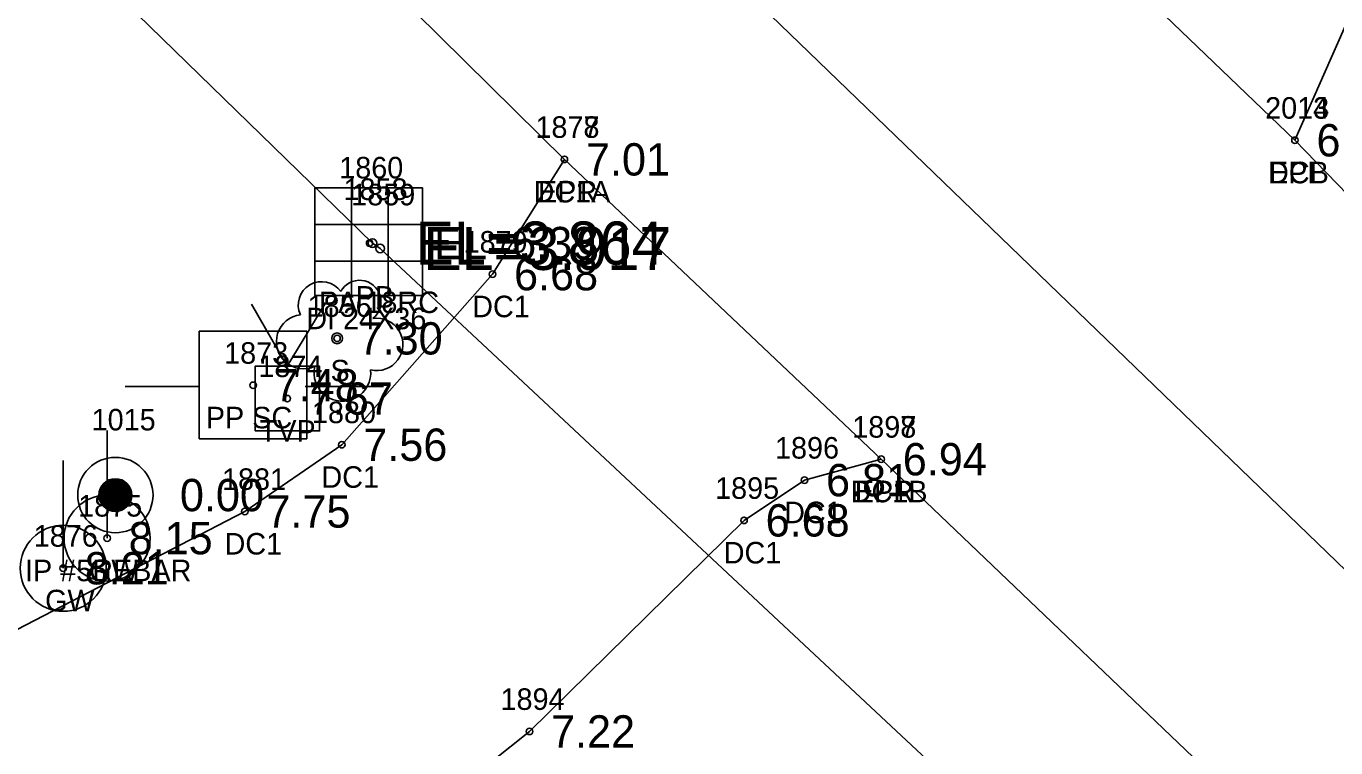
# Model space of a CAD drawing. Extents: x 2608598 to 2610682, y 641451 to 643526.
# Drawn here: x 2609158.2 to 2609219, y 642975 to 643008.5 of the extents above; entities that cross this region are included whole.
import ezdxf

# ---------------------------------------------------------------- set-up
doc = ezdxf.new("R2010")
doc.units = 0
for name, color, linetype in [('RD_EX_Conc', 7, 'Continuous'), ('RD_EX_Conc_txCode', 7, 'Continuous'), ('RD_EX_DR_Inlet', 7, 'Continuous'), ('RD_EX_DR_Inlet_txCode', 7, 'Continuous'), ('RD_EX_DR_Pipe', 7, 'Continuous'), ('RD_EX_DR_Pipe_txCode', 7, 'Continuous'), ('RD_EX_DV_Prop_txCode', 7, 'Continuous'), ('RD_EX_DV_PropPin', 7, 'Continuous'), ('RD_EX_Road', 7, 'Continuous'), ('RD_EX_Road_txCode', 7, 'Continuous'), ('RD_EX_TX_Conc_ELEV', 7, 'Continuous'), ('RD_EX_TX_DR_Inlet_ELEV', 7, 'Continuous'), ('RD_EX_TX_DV_Prop_ELEV', 7, 'Continuous'), ('RD_EX_TX_Road_ELEV', 7, 'Continuous'), ('RD_EX_TX_UT_ELEV', 7, 'Continuous'), ('RD_EX_TX_VEG_ELEV', 7, 'Continuous'), ('RD_EX_UT', 7, 'Continuous'), ('RD_EX_UT_txCode', 7, 'Continuous'), ('RD_EX_VEG', 7, 'Continuous'), ('RD_EX_VEG_txCode', 7, 'Continuous'), ('RD_HC_Cl', 7, 'Continuous'), ('RD_HC_Survey_ELEV', 7, 'Continuous'), ('RD_SMD_Locator', 7, 'Continuous'), ('RD_TX_Pipe_ElevEX', 7, 'Continuous')]:
    doc.layers.add(name, color=color, linetype=linetype)

msp = doc.modelspace()

# ---------------------------------------------------------------- linework, layer by layer
at = {"layer": 'RD_EX_Conc'}
for points in [[(2609269.998, 643061.086), (2609272.605, 643058.59), (2609260.564, 643044.702), (2609257.72, 643041.969), (2609255.041, 643040.51), (2609251.591, 643039.846), (2609247.634, 643039.744), (2609244.983, 643039.005), (2609242.031, 643037.037), (2609225.849, 643019.544), (2609223.428, 643016.615), (2609221.422, 643012.887), (2609217.132, 643003.172)], [(2609183.195, 643002.284), (2609179.855, 642996.956), (2609172.851, 642989.038), (2609168.35, 642985.939), (2609153.064, 642978.036), (2609140.288, 642969.219), (2609118.234, 642952.787)], [(2609162.68, 642959.754), (2609163.773, 642962.47), (2609165.522, 642965.128), (2609168.171, 642967.213), (2609174.254, 642970.662), (2609178.069, 642972.943), (2609181.572, 642975.727), (2609191.54, 642985.525), (2609194.348, 642987.393), (2609197.913, 642988.365)]]:
    msp.add_lwpolyline(points, dxfattribs=at)
at = {"layer": 'RD_EX_DR_Inlet'}
for p, q in [((2609173.304, 643000.957), (2609173.304, 642995.957)), ((2609175.004, 643000.957), (2609175.004, 642995.957)), ((2609171.604, 642999.257), (2609176.604, 642999.257)), ((2609171.604, 642997.557), (2609176.604, 642997.557))]:
    msp.add_line(p, q, dxfattribs=at)
msp.add_lwpolyline([(2609171.604, 642995.957), (2609171.604, 643000.957), (2609176.604, 643000.957), (2609176.604, 642995.957)], close=True, dxfattribs=at)
at = {"layer": 'RD_EX_DR_Pipe'}
msp.add_lwpolyline([(2609067.894, 643101.844), (2609174.278, 642998.399), (2609174.637, 642998.15), (2609264.347, 642914.358)], dxfattribs=at)
at = {"layer": 'RD_EX_DV_PropPin'}
for p, q in [((2609161.667, 642986.33), (2609161.667, 642987.069)), ((2609161.702, 642986.273), (2609161.702, 642987.126)), ((2609161.737, 642986.226), (2609161.737, 642987.174)), ((2609161.772, 642986.185), (2609161.772, 642987.215)), ((2609161.807, 642986.149), (2609161.807, 642987.25)), ((2609161.842, 642986.118), (2609161.842, 642987.282)), ((2609161.877, 642986.09), (2609161.877, 642987.31)), ((2609161.912, 642986.065), (2609161.912, 642987.334)), ((2609161.947, 642986.043), (2609161.947, 642987.356)), ((2609161.982, 642986.024), (2609161.982, 642987.375)), ((2609162.017, 642986.007), (2609162.017, 642987.392)), ((2609162.052, 642985.992), (2609162.052, 642987.407)), ((2609162.087, 642985.979), (2609162.087, 642987.42)), ((2609162.122, 642985.968), (2609162.122, 642987.431)), ((2609162.157, 642985.959), (2609162.157, 642987.44)), ((2609162.192, 642985.952), (2609162.192, 642987.448)), ((2609162.227, 642985.946), (2609162.227, 642987.453)), ((2609162.262, 642985.942), (2609162.262, 642987.457)), ((2609162.297, 642985.939), (2609162.297, 642987.46)), ((2609162.332, 642985.939), (2609162.332, 642987.461)), ((2609162.367, 642985.939), (2609162.367, 642987.46)), ((2609162.402, 642985.942), (2609162.402, 642987.457)), ((2609162.437, 642985.946), (2609162.437, 642987.453)), ((2609162.472, 642985.952), (2609162.472, 642987.448)), ((2609162.507, 642985.959), (2609162.507, 642987.44)), ((2609162.542, 642985.968), (2609162.542, 642987.431)), ((2609162.577, 642985.979), (2609162.577, 642987.42)), ((2609162.612, 642985.992), (2609162.612, 642987.407)), ((2609162.647, 642986.007), (2609162.647, 642987.392)), ((2609162.682, 642986.024), (2609162.682, 642987.375)), ((2609162.717, 642986.043), (2609162.717, 642987.356)), ((2609162.752, 642986.065), (2609162.752, 642987.334)), ((2609162.787, 642986.09), (2609162.787, 642987.31)), ((2609162.822, 642986.118), (2609162.822, 642987.282)), ((2609162.857, 642986.149), (2609162.857, 642987.25)), ((2609162.893, 642986.185), (2609162.893, 642987.215)), ((2609162.928, 642986.226), (2609162.928, 642987.174)), ((2609162.963, 642986.273), (2609162.963, 642987.126)), ((2609162.998, 642986.33), (2609162.998, 642987.069)), ((2609161.597, 642986.504), (2609161.597, 642986.896)), ((2609161.632, 642986.402), (2609161.632, 642986.998)), ((2609163.033, 642986.402), (2609163.033, 642986.998)), ((2609163.068, 642986.504), (2609163.068, 642986.896))]:
    msp.add_line(p, q, dxfattribs=at)
for radius in [1.75, 0.761]:
    msp.add_circle((2609162.332, 642986.7), radius, dxfattribs=at)
at = {"layer": 'RD_EX_Road'}
for points in [[(2608806.889, 643364.989), (2608810.184, 643361.1), (2608820.754, 643351.249), (2608881.81, 643292.235), (2608917.833, 643257.495), (2608933.208, 643242.709), (2608954.068, 643222.833), (2609026.064, 643154.189), (2609039.601, 643139.963), (2609073.879, 643106.954), (2609100.48, 643081.888), (2609124.194, 643058.866), (2609171.612, 643013.711), (2609183.195, 643002.284), (2609197.913, 642988.365), (2609247.586, 642940.954), (2609328.02, 642863.599), (2609402.609, 642790.299), (2609474.235, 642720.69), (2609483.838, 642711.579), (2609495.782, 642699.917), (2609509.808, 642686.45)], [(2609042.495, 643170.94), (2609058.512, 643155.458), (2609096.06, 643119.372), (2609116.51, 643099.11), (2609162.396, 643055.351), (2609177.209, 643041.342), (2609188.353, 643030.959), (2609199.912, 643019.764), (2609205.803, 643014.044), (2609217.132, 643003.172), (2609235.835, 642983.899), (2609237.032, 642983.51), (2609256.803, 642965.042), (2609258.491, 642962.514), (2609263.653, 642957.664), (2609344.713, 642879.888)]]:
    msp.add_lwpolyline(points, dxfattribs=at)
at = {"layer": 'RD_EX_UT'}
for p, q in [((2609170.321, 642992.678), (2609168.655, 642995.564)), ((2609170.321, 642992.678), (2609172.062, 642995.564)), ((2609171.223, 642994.306), (2609166.223, 642994.306)), ((2609166.223, 642994.306), (2609166.223, 642989.306)), ((2609171.223, 642989.306), (2609171.223, 642994.306)), ((2609162.791, 642991.744), (2609166.261, 642991.744)), ((2609171.151, 642991.744), (2609174.791, 642991.744)), ((2609161.949, 642984.701), (2609161.949, 642989.701)), ((2609166.223, 642989.306), (2609171.223, 642989.306)), ((2609159.91, 642983.303), (2609159.91, 642988.303))]:
    msp.add_line(p, q, dxfattribs=at)
msp.add_lwpolyline([(2609168.821, 642989.678), (2609168.821, 642992.678), (2609171.821, 642992.678), (2609171.821, 642989.678)], close=True, dxfattribs=at)
for centre in [(2609161.949, 642984.701), (2609159.91, 642983.303)]:
    msp.add_circle(centre, 1.999, dxfattribs=at)
at = {"layer": 'RD_EX_VEG'}
msp.add_circle((2609172.633, 642993.975), 0.25, dxfattribs=at)
for centre, radius, start, end in [((2609171.912, 642995.522), 1.084, 34.97629, 204.75602), ((2609173.678, 642995.677), 0.995, 308.76261, 152.04674), ((2609171.069, 642993.819), 1.257, 96.45179, 294.73401), ((2609174.472, 642993.696), 1.218, 256.56668, 98.10463), ((2609172.878, 642992.379), 1.318, 166.88266, 5.75893)]:
    msp.add_arc(centre, radius, start, end, dxfattribs=at)
at = {"layer": 'RD_HC_Cl'}
msp.add_line((2608814.812, 643373.733), (2610092.394, 642140.787), dxfattribs=at)
at = {"layer": 'RD_SMD_Locator'}
for centre, radius in [((2609217.132, 643003.172), 0.15), ((2609217.132, 643003.172), 0.15), ((2609183.195, 643002.284), 0.15), ((2609183.195, 643002.284), 0.15), ((2609174.142, 642998.399), 0.15), ((2609174.278, 642998.399), 0.2), ((2609174.637, 642998.15), 0.2), ((2609179.855, 642996.956), 0.15), ((2609172.633, 642993.975), 0.15), ((2609168.732, 642991.797), 0.15), ((2609170.321, 642991.178), 0.15), ((2609172.851, 642989.038), 0.15), ((2609197.913, 642988.365), 0.15), ((2609197.913, 642988.365), 0.15), ((2609194.348, 642987.393), 0.15), ((2609162.332, 642986.7), 0.15), ((2609168.35, 642985.939), 0.15), ((2609191.54, 642985.525), 0.15), ((2609161.949, 642984.701), 0.15), ((2609159.91, 642983.303), 0.15), ((2609181.572, 642975.727), 0.15)]:
    msp.add_circle(centre, radius, dxfattribs=at)

# ---------------------------------------------------------------- texts
at = {"layer": 'RD_EX_Conc_txCode'}
for s, p in [('2013', (2609215.747, 643004.172)), ('1878', (2609181.848, 643003.284)), ('DCB', (2609215.881, 643001.172)), ('DC1A', (2609181.762, 643000.284)), ('1879', (2609178.509, 642997.956)), ('DC1', (2609178.91, 642994.956)), ('1880', (2609171.465, 642990.038)), ('1897', (2609196.566, 642989.365)), ('1896', (2609192.978, 642988.393)), ('1881', (2609167.287, 642986.939)), ('DC1', (2609171.906, 642987.038)), ('1895', (2609190.194, 642986.525)), ('DC1B', (2609196.495, 642986.365)), ('DC1', (2609193.403, 642985.393)), ('DC1', (2609167.405, 642983.939)), ('DC1', (2609190.595, 642983.525)), ('1894', (2609180.226, 642976.727))]:
    msp.add_text(s, height=1, dxfattribs=at).set_placement(p)
at = {"layer": 'RD_EX_DR_Inlet_txCode'}
for s, p in [('1860', (2609172.733, 643001.399)), ('DI 24X36', (2609171.205, 642994.399))]:
    msp.add_text(s, height=1, dxfattribs=at).set_placement(p)
at = {"layer": 'RD_EX_DR_Pipe_txCode'}
for s, p in [('1858', (2609172.931, 643000.399)), ('1859', (2609173.29, 643000.15)), ('PB', (2609173.498, 642995.399)), ('PA 18RC', (2609171.794, 642995.15))]:
    msp.add_text(s, height=1, dxfattribs=at).set_placement(p)
at = {"layer": 'RD_EX_DV_Prop_txCode'}
for s, p in [('1015', (2609161.23, 642989.7)), ('IP #5REBAR', (2609158.135, 642982.7))]:
    msp.add_text(s, height=1, dxfattribs=at).set_placement(p)
at = {"layer": 'RD_EX_Road_txCode'}
for s, p in [('2014', (2609215.747, 643004.172)), ('1877', (2609181.848, 643003.284)), ('EPL', (2609215.928, 643001.172)), ('EPR', (2609181.966, 643000.284)), ('1898', (2609196.566, 642989.365)), ('EPR', (2609196.684, 642986.365))]:
    msp.add_text(s, height=1, dxfattribs=at).set_placement(p)
at = {"layer": 'RD_EX_TX_Conc_ELEV'}
for s, p in [('6.82', (2609218.132, 643002.422)), ('7.01', (2609184.195, 643001.534)), ('6.68', (2609180.855, 642996.206)), ('7.56', (2609173.851, 642988.288)), ('6.94', (2609198.913, 642987.615)), ('6.81', (2609195.348, 642986.643)), ('7.75', (2609169.35, 642985.189)), ('6.68', (2609192.54, 642984.775)), ('7.22', (2609182.572, 642974.977))]:
    msp.add_text(s, height=1.5, dxfattribs=at).set_placement(p)
at = {"layer": 'RD_EX_TX_DR_Inlet_ELEV'}
msp.add_text('EL=6.39', height=1.5, dxfattribs=at).set_placement((2609177.142, 642997.649))
at = {"layer": 'RD_EX_TX_DV_Prop_ELEV'}
msp.add_text('0.00', height=1.5, dxfattribs=at).set_placement((2609165.332, 642985.95))
at = {"layer": 'RD_EX_TX_Road_ELEV'}
for s, p in [('6.82', (2609218.132, 643002.422)), ('7.01', (2609184.195, 643001.534)), ('6.94', (2609198.913, 642987.615))]:
    msp.add_text(s, height=1.5, dxfattribs=at).set_placement(p)
at = {"layer": 'RD_EX_TX_UT_ELEV'}
for s, p in [('7.67', (2609171.321, 642990.428)), ('8.15', (2609162.949, 642983.951)), ('8.21', (2609160.91, 642982.553))]:
    msp.add_text(s, height=1.5, dxfattribs=at).set_placement(p)
at = {"layer": 'RD_EX_TX_VEG_ELEV'}
msp.add_text('7.30', height=1.5, dxfattribs=at).set_placement((2609173.633, 642993.225))
at = {"layer": 'RD_EX_UT_txCode'}
for s, p in [('1873', (2609167.385, 642992.797)), ('1874', (2609168.975, 642992.178)), ('PP SC', (2609166.535, 642989.797)), ('TVP', (2609169.038, 642989.178)), ('1875', (2609160.603, 642985.701)), ('1876', (2609158.54, 642984.303)), ('GW', (2609161.107, 642982.701)), ('GW', (2609159.068, 642981.303))]:
    msp.add_text(s, height=1, dxfattribs=at).set_placement(p)
at = {"layer": 'RD_EX_VEG_txCode'}
for s, p in [('1856', (2609171.263, 642994.975)), ('S', (2609172.326, 642991.975))]:
    msp.add_text(s, height=1, dxfattribs=at).set_placement(p)
at = {"layer": 'RD_HC_Survey_ELEV'}
msp.add_text('7.48', height=1.5, dxfattribs=at).set_placement((2609169.732, 642991.047))
at = {"layer": 'RD_TX_Pipe_ElevEX'}
for s, p in [('EL=3.864', (2609176.278, 642997.399)), ('EL=3.917', (2609176.637, 642997.15))]:
    msp.add_text(s, height=2, dxfattribs=at).set_placement(p)

doc.saveas('drawing.dxf')
